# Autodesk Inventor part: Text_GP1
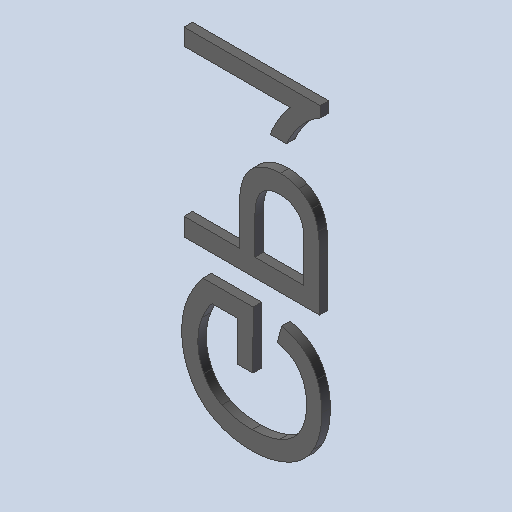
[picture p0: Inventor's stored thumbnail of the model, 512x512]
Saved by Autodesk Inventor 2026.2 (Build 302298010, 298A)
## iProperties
Created: 2026-10
Part Number: Text_GP1
Material: Générique
Document SubType Name: Modeling
Designer: mel
Density: 1 g/cm^3
Appearance: Par défaut
Author: mel
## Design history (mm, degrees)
feature "Base1"
feature "Base2"
feature "Base3"
node "Solide1"
node "Solide2"
node "Solide3"
